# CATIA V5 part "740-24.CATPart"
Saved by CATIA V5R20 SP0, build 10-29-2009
Part number: 740-24
Bounding box of the stored display mesh (mm): x -23.9 to 23.9, y -22 to 23.845, z -23 to 12
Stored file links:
  C:\Users\Utente\Desktop\IO LAVORO\3D X SITO CF\X SITO\740\740-24.CATPart
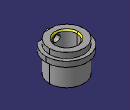
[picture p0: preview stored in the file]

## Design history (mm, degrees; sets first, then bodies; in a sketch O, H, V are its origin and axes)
Set1
  DatumSurface1 to DatumSurface35 "740-24"
Body1 (main body)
